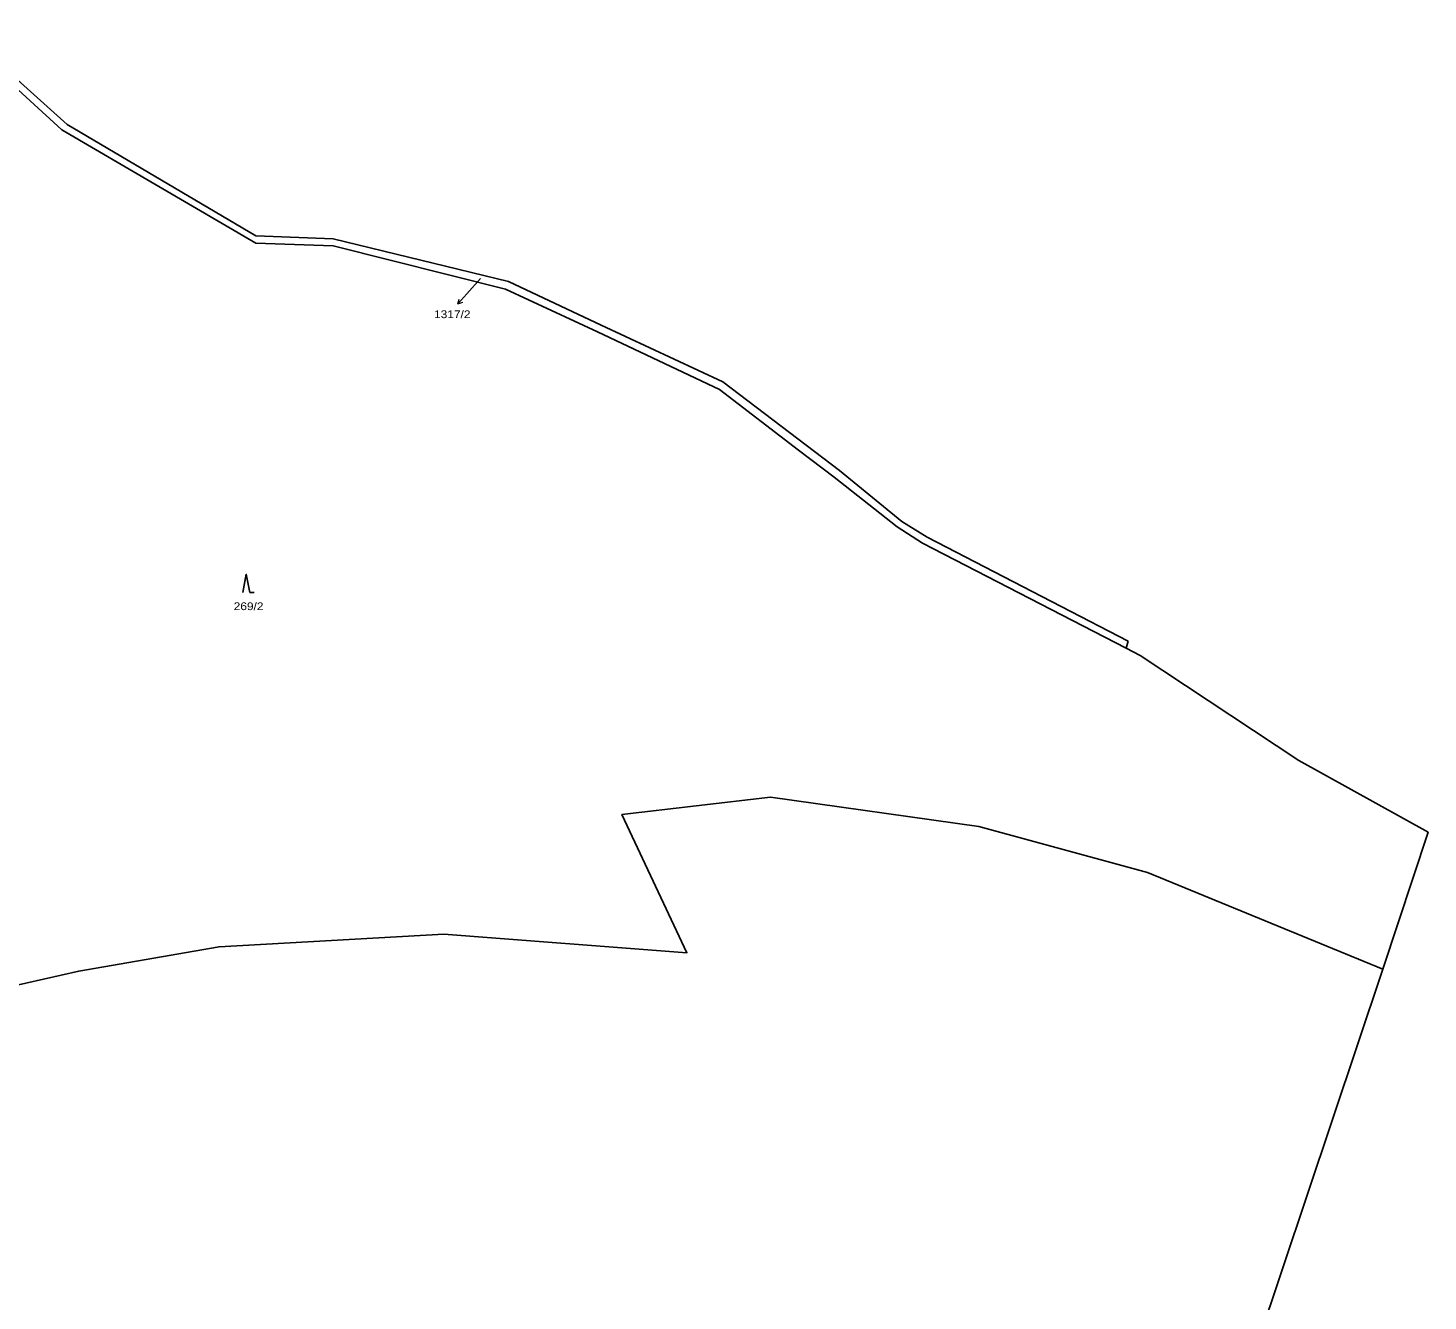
# Model space of a CAD drawing. Extents: x -872229 to -869198, y -1075981 to -1074329.
# Drawn here: x -869694.9 to -869387.3, y -1074938.2 to -1074658.6 of the extents above; entities that cross this region are included whole.
import ezdxf
from ezdxf.enums import TextEntityAlignment as Align

# ---------------------------------------------------------------- set-up
doc = ezdxf.new("R2010")
doc.units = 0
doc.header["$LTSCALE"] = 0.68
for name, color, linetype, lineweight in [('1', 7, 'Continuous', 25), ('3', 7, 'Continuous', 25), ('7', 7, 'Continuous', 13)]:
    doc.layers.add(name, color=color, linetype=linetype, lineweight=lineweight)
doc.layers.add('2', color=7, linetype='Continuous')

msp = doc.modelspace()

# ---------------------------------------------------------------- linework, layer by layer
at = {"layer": '1'}
msp.add_line((-869453.23, -1074793.29), (-869453.66, -1074794.85), dxfattribs=at)
for points in [[(-869453.23, -1074793.29), (-869497.35, -1074770.43), (-869502.91, -1074766.99), (-869516.66, -1074755.78), (-869542.23, -1074736.35), (-869569.01, -1074723.84), (-869589.32, -1074714.31), (-869627.88, -1074704.89), (-869644.84, -1074704.23), (-869686.29, -1074679.82), (-869709.86, -1074658.59), (-869711.15, -1074659.32)], [(-869453.66, -1074794.85), (-869498.36, -1074771.77), (-869503.98, -1074768.2), (-869517.76, -1074757.22), (-869525.6, -1074751.31), (-869543.02, -1074738.02), (-869569.82, -1074725.31), (-869590.03, -1074715.95), (-869627.87, -1074706.45), (-869644.88, -1074705.89), (-869687.49, -1074680.97), (-869701.44, -1074668.21)], [(-869453.66, -1074794.85), (-869450.55, -1074796.46), (-869415.69, -1074819.52)], [(-869415.69, -1074819.52), (-869387.33, -1074835.26), (-869397.27, -1074865.36), (-869463.59, -1075063.5)], [(-869397.27, -1074865.36), (-869448.98, -1074844.13), (-869486.01, -1074834.03), (-869531.78, -1074827.54), (-869564.41, -1074831.36), (-869550.14, -1074861.73), (-869603.53, -1074857.64), (-869652.94, -1074860.42), (-869683.77, -1074865.74), (-869722.65, -1074874.59), (-869772.21, -1074877.32), (-869775.77, -1074861.05), (-869776.86, -1074851.73)]]:
    msp.add_lwpolyline(points, dxfattribs=at)
at = {"layer": '3'}
msp.add_line((-869646.21, -1074782.6), (-869645.214, -1074782.6), dxfattribs=at)
msp.add_lwpolyline([(-869646.21, -1074782.6), (-869646.96, -1074778.6), (-869647.71, -1074782.6)], dxfattribs=at)
at = {"layer": '7'}
msp.add_line((-869600.449, -1074719.215), (-869599.414, -1074718.788), dxfattribs=at)
msp.add_lwpolyline([(-869595.53, -1074713.6), (-869598.48, -1074716.95), (-869600.449, -1074719.215), (-869600.17, -1074718.131)], dxfattribs=at)

# ---------------------------------------------------------------- texts
at = {"layer": '2', "width": 1.15}
msp.add_text('1317/2', height=1.7, dxfattribs=at).set_placement((-869601.699, -1074722.32), align=Align.CENTER)
msp.add_text('269/2', height=1.7, dxfattribs=at).set_placement((-869649.72, -1074786.46))

doc.saveas('drawing.dxf')
